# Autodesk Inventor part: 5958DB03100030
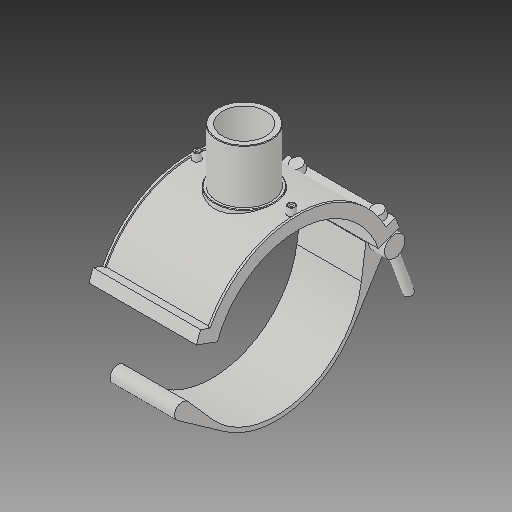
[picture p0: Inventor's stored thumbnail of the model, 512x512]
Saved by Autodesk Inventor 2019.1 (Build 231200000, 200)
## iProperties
Created: 2017-07
Part Number: 5958DB03100030
Material: Generic
Description: PLASSON BRANCH SADDLE 10''DIPS x 3''IPS
Document SubType Name: Modeling
Designer: KIM
Mass: 764.267 g
Surface Area: 1930.38 cm^2
Volume: 764.267 cm^3
Density: 1 g/cm^3
Appearance: Default
Author: KIM
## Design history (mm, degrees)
derived "5958D (2).ipt"
feature "Solid6::5958D (2).ipt"
tag "TaggingFeature1"
body "Solid1"
other parameters: "d_" = 280.6, "d1" = 88.7, "B_" = 180.594, "H_" = 106.934, "H1" = 88.646, "L" = 176.022, "t" = 6, "d244" = 280.6, "d245" = 18.288, "d248" = 180.594, "d249" = 90.297, "d252" = 140.3, "d254" = 18.288, "d256" = 541.782, "d257" = 35.075, "d258" = 270.891, "d259" = 0.5, "d260" = 176.022, "d261" = 0, "d287" = 159.31952, "d288" = 97.57, "d290" = 0, "d291" = 247.234, "d292" = 88.7, "d294" = 0, "d309" = 170.3, "d310" = 12, "d311" = 12, "d315" = 3 deg, "d316" = 4, "d318" = 4, "d320" = 14, "d321" = 0, "d331" = 0.887, "d332" = 70.96, "d334" = 0, "d337" = 0.887, "d340" = 10.56132, "d341" = 10.56132, "d342" = 20 deg, "d343" = 20 deg, "d344" = 722.376, "d345" = 280.6, "d347" = 0, "d352" = 36.576, "d353" = 19.642, "d355" = 0, "d356" = 20 deg, "d357" = 42.09, "d358" = 280.6, "d359" = 294.63, "d360" = 33.672, "d361" = 10 deg, "d362" = 8.13816, "d363" = 56.12, "d366" = 154.33, "d367" = 8.50392, "d368" = 105.6132, "d369" = 0, "d370" = 158.4198, "d371" = 0, "d372" = 132.0165, "d374" = 14.03, "d375" = 19.642, "d376" = 14.03, "d377" = 19.642, "d378" = 140.3, "d379" = 0, "d380" = 11.7852, "d381" = 0, "d383" = 167.732, "d384" = 17.6022, "d385" = 2.806, "d386" = 3.52044, "d387" = 0, "d389" = 360 deg
